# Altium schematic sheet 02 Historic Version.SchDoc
size 297 x 209 mm
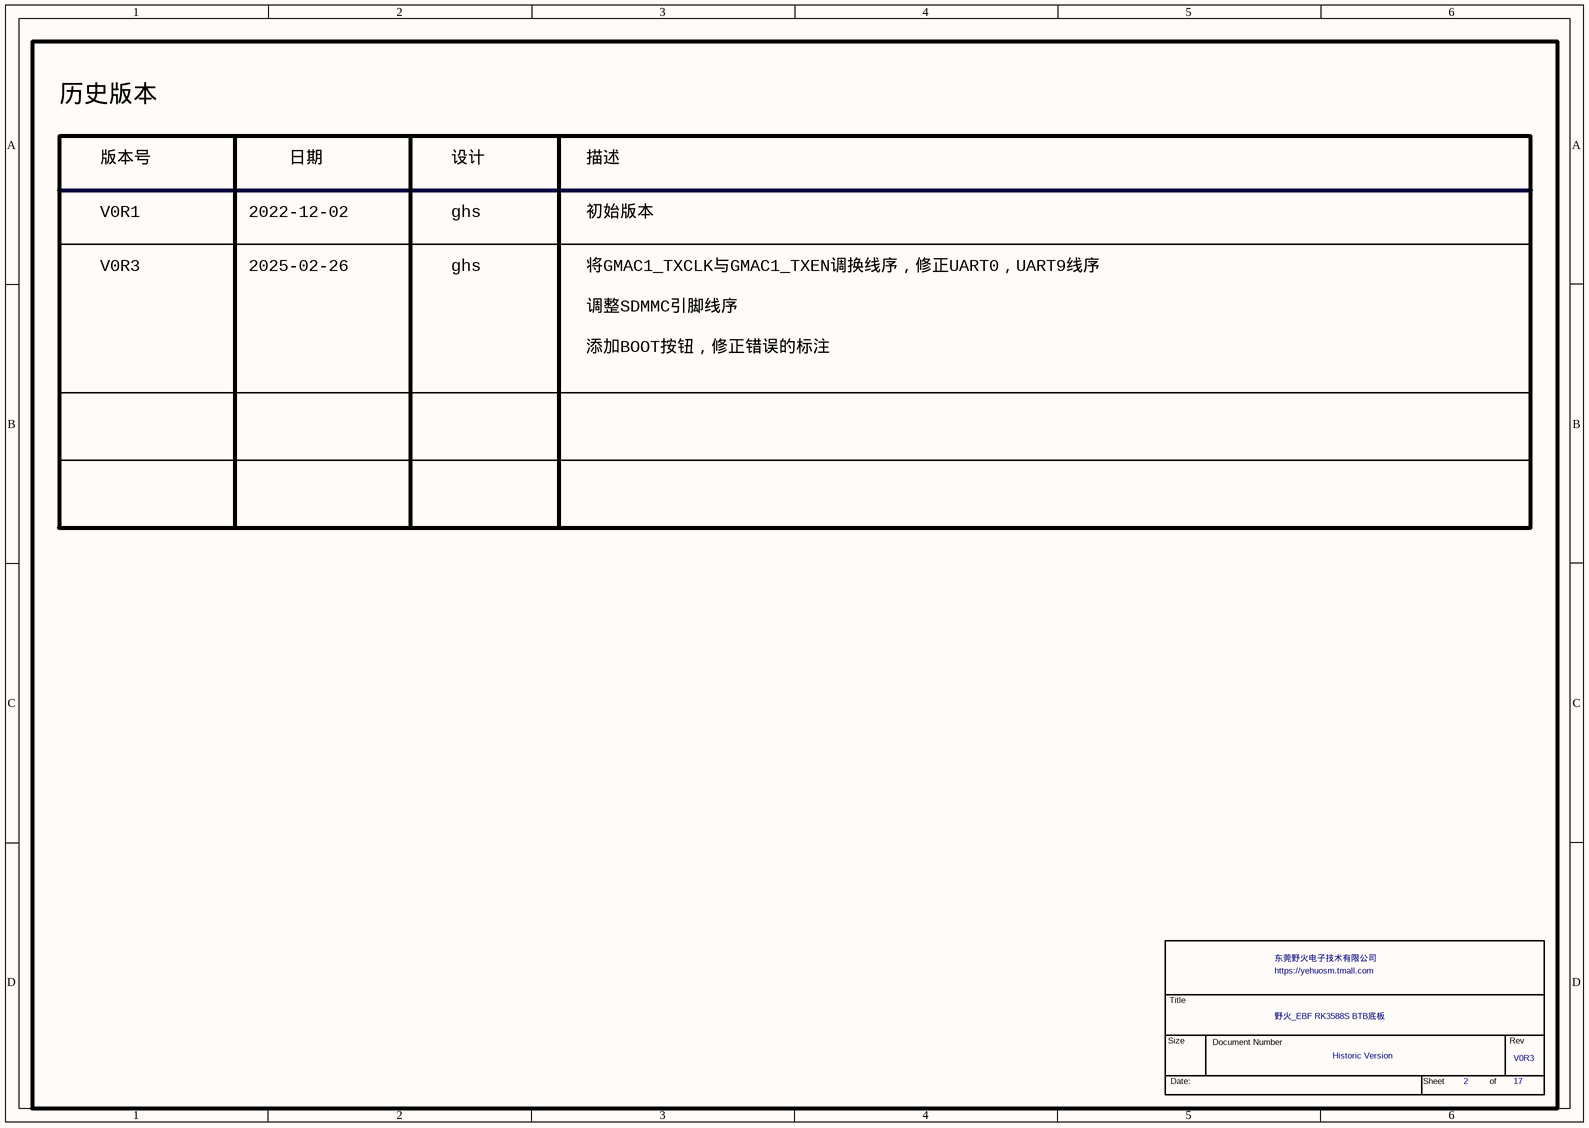
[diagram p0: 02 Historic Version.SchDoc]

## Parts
*  Page Count: 17  Page Number: 2  OrgName: 东莞野火电子技术有限公司  Title: 野火_EBF RK3588S BTB底板  RevCode: V0R3  Doc: Historic Version  (hidden comment: TitleBlock_YHSCH)  (graphical)

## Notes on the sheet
- 历史版本
- 版本号
- 日期
- 设计
- 描述
- V0R1
- V0R3
- 2022-12-02
- 2025-02-26
- ghs
- 初始版本
- 将GMAC1_TXCLK与GMAC1_TXEN调换线序，修正UART0，UART9线序
- 调整SDMMC引脚线序
- 添加BOOT按钮，修正错误的标注

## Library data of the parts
* = TitleBlock_YHSCH: Cage Code: 1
